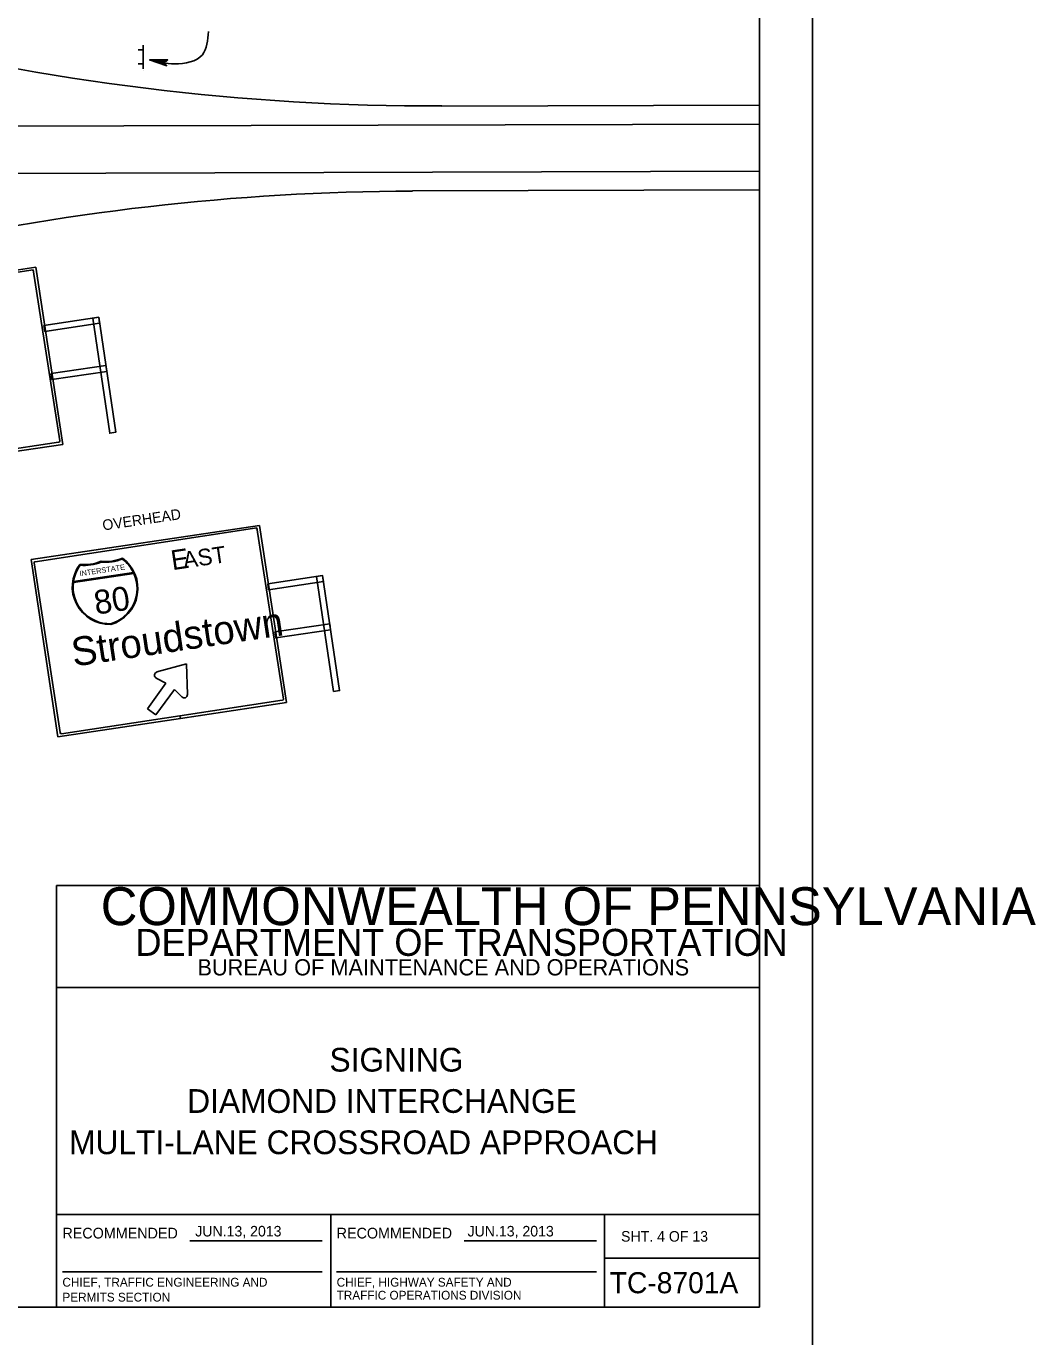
# Model space of a CAD drawing. Extents: x 644898 to 648326, y 298294 to 300670.
# Drawn here: x 648038.7 to 648325.9, y 300083.1 to 300456 of the extents above; entities that cross this region are included whole.
import ezdxf

# ---------------------------------------------------------------- set-up
doc = ezdxf.new("R2010")
doc.units = 0
for name, color, linetype in [('1', 7, 'Continuous'), ('2', 7, 'Continuous'), ('XCS-GRID-MIN', 7, 'Continuous')]:
    doc.layers.add(name, color=color, linetype=linetype)

msp = doc.modelspace()

# ---------------------------------------------------------------- linework, layer by layer
at = {"layer": '1'}
for p, q in [((648247.32, 300091.49), (648247.32, 300655.49)), ((648047.32, 300091.49), (648047.32, 300211.49)), ((648047.32, 300211.49), (648247.32, 300211.49)), ((648247.32, 300182.49), (648047.32, 300182.49)), ((648047.32, 300117.87), (648247.32, 300117.87)), ((648125.32, 300117.87), (648125.32, 300091.49)), ((648203.2, 300091.49), (648203.2, 300117.87)), ((648085.26, 300110.44), (648122.88, 300110.44)), ((648163.26, 300110.44), (648200.88, 300110.44)), ((648203.2, 300105.49), (648247.32, 300105.49)), ((648049.01, 300101.54), (648122.88, 300101.54)), ((648127.01, 300101.54), (648200.88, 300101.54)), ((648247.32, 300091.49), (647461.32, 300091.49)), ((647461.32, 300091.49), (648047.32, 300091.49))]:
    msp.add_line(p, q, dxfattribs=at)
at = {"layer": '2'}
for p, q in [((648071.95, 300450.62), (648071.95, 300443.87)), ((648071.95, 300449.24), (648070.57, 300449.24)), ((648071.95, 300445.24), (648070.57, 300445.24)), ((648071.95, 300443.49), (648071.95, 300443.49)), ((648071.95, 300443.49), (648071.95, 300443.49)), ((648156.95, 300433.24), (648247.32, 300433.51)), ((648242.07, 300433.49), (648242.07, 300433.49)), ((647844.32, 300426.99), (648247.32, 300428.13)), ((647846.32, 300413.49), (648247.32, 300414.76)), ((648148.57, 300409.12), (648247.32, 300409.38)), ((647976.44, 300377.72), (648041.41, 300387.38)), ((648048.26, 300338.02), (648040.68, 300386.7)), ((648041.41, 300387.38), (648049.11, 300337)), ((648018.78, 300333.23), (648047.9, 300337.67)), ((648049.11, 300337), (648018.89, 300332.5)), ((648040.09, 300304.24), (648105.06, 300313.9)), ((648111.92, 300264.54), (648104.33, 300313.23)), ((648105.06, 300313.9), (648112.77, 300263.52)), ((648047.7, 300253.84), (648040.09, 300304.25)), ((648065.99, 300304.39), (648065.99, 300304.39)), ((648041, 300303.26), (648048.35, 300255.06)), ((648069.23, 300300.51), (648052.19, 300298)), ((648054.06, 300302.57), (648054.06, 300302.57)), ((648060.07, 300303.49), (648060.07, 300303.49)), ((648052.17, 300297.71), (648069.3, 300300.25)), ((648084.32, 300274.56), (648075.86, 300272.27)), ((648084.55, 300265.87), (648084.32, 300274.56)), ((648078.38, 300269.07), (648073.2, 300261.79)), ((648075.56, 300260.01), (648080.89, 300267.24)), ((648075.63, 300270.44), (648078.38, 300269.07)), ((648080.89, 300267.24), (648082.95, 300265.18)), ((648082.44, 300259.76), (648111.56, 300264.2)), ((648112.77, 300263.52), (648082.55, 300259.03)), ((648048.74, 300254.69), (648082.44, 300259.76)), ((648073.2, 300261.79), (648075.56, 300260.01)), ((648082.55, 300259.03), (648082.44, 300259.76)), ((648082.44, 300259.76), (648082.55, 300259.03)), ((648082.55, 300259.03), (648047.7, 300253.84))]:
    msp.add_line(p, q, dxfattribs=at)
for points in [[(648078.45, 300444.99), (648078.32, 300445.37), (648073.82, 300446.37), (648078.45, 300444.99), (648078.7, 300444.74), (648073.82, 300446.37), (648078.45, 300445.87), (648078.7, 300446.12), (648073.82, 300446.37), (648078.95, 300446.37), (648078.7, 300446.12)], [(648040.68, 300386.7), (647977.64, 300377.08)], [(648104.33, 300313.23), (648041.29, 300303.61)]]:
    msp.add_lwpolyline(points, dxfattribs=at)
for points in [[(648043.74, 300370.85), (648059.34, 300373.16), (648059.59, 300371.45), (648043.99, 300369.13)], [(648059.34, 300373.16), (648064.2, 300340.43), (648062.49, 300340.18), (648057.63, 300372.91)], [(648045.77, 300357.14), (648061.37, 300359.46), (648061.63, 300357.75), (648046.03, 300355.43)], [(648107.39, 300297.37), (648122.99, 300299.69), (648123.25, 300297.98), (648107.64, 300295.66)], [(648122.99, 300299.69), (648127.86, 300266.96), (648126.14, 300266.71), (648121.28, 300299.43)], [(648109.43, 300283.67), (648125.03, 300285.99), (648125.28, 300284.27), (648109.68, 300281.96)]]:
    msp.add_lwpolyline(points, close=True, dxfattribs=at)
for centre, radius, start, end in [((648154.92, 301105.15), 671.88, 255.77937, 270.1682), ((648150.55, 299737.19), 671.88, 90.1683, 103.0152), ((648076.11, 300271.33), 0.915, 103.9183, 245.5492), ((648083.64, 300265.78), 0.915, 225, 1.3737)]:
    msp.add_arc(centre, radius, start, end, dxfattribs=at)
for centre, major_axis, ratio, start_param, end_param in [((648040.43, 300386.16), (-0.388, 0), 0.989072, 3.283634, 4.860778), ((648047.88, 300337.97), (0.361, 0.041), 0.980329, 4.753008, 6.326457), ((648104.08, 300312.69), (-0.388, 0), 0.989072, 3.283634, 4.860778), ((648061.23, 300316), (12.46, 0), 0.989072, 4.61309, 5.11051), ((648061.23, 300316), (12.69, 0), 0.989072, 4.617647, 5.100204), ((648059.62, 300296.01), (10.85, 0), 0.989072, 5.003697, 7.217995), ((648059.62, 300296.01), (10.62, 0), 0.989072, 0.4425, 0.922725), ((648041.33, 300303.28), (-0.388, 0), 0.989072, 4.856969, 6.450662), ((648062.66, 300296.46), (-10.85, 0), 0.989072, 5.647198, 7.861496), ((648062.66, 300296.46), (-10.62, 0), 0.989072, 5.659282, 6.139508), ((648055.16, 300315.1), (-12.46, 0), 0.989072, 1.471498, 1.968918), ((648055.16, 300315.1), (-12.69, 0), 0.989072, 1.481804, 1.964361), ((648062.66, 300296.46), (-10.62, 0), 0.989072, 6.161841, 7.861496), ((648059.62, 300296.01), (10.62, 0), 0.989072, 5.003697, 6.703352), ((648111.53, 300264.5), (0.361, 0.041), 0.980329, 4.753008, 6.326457), ((648048.7, 300255.1), (-0.402, -0.077), 0.953585, 6.234444, 7.82518)]:
    msp.add_ellipse(centre, major_axis=major_axis, ratio=ratio, start_param=start_param, end_param=end_param, dxfattribs=at)
msp.add_spline([(648090.57, 300454.49), (648088.82, 300447.87), (648080.95, 300445.24), (648073.82, 300446.37)], degree=3, dxfattribs=at)
at = {"layer": 'XCS-GRID-MIN'}
msp.add_lwpolyline([(647421.32, 300670.49), (648262.32, 300670.49), (648262.32, 300076.49), (647421.32, 300076.49)], close=True, dxfattribs=at)

# ---------------------------------------------------------------- texts
at = {"layer": '1'}
for s, height, p in [('COMMONWEALTH OF PENNSYLVANIA', 10.7828, (648059.92, 300200.22)), ('DEPARTMENT OF TRANSPORTATION', 7.6837, (648069.78, 300191.48)), ('BUREAU OF MAINTENANCE AND OPERATIONS', 4.6253, (648087.42, 300185.91)), ('SIGNING', 6.75, (648124.97, 300158.56)), ('DIAMOND INTERCHANGE', 6.75, (648084.5, 300146.81)), ('MULTI-LANE CROSSROAD APPROACH', 6.75, (648050.91, 300135.06)), ('RECOMMENDED', 3.048, (648049.01, 300111.07)), ('RECOMMENDED', 3.048, (648127.01, 300111.07)), ('SHT. 4 OF 13', 3, (648207.91, 300110.18)), ('CHIEF, TRAFFIC ENGINEERING AND', 2.5, (648049.01, 300097.38)), ('CHIEF, HIGHWAY SAFETY AND', 2.5, (648127.01, 300097.38)), ('TC-8701A', 6, (648204.69, 300095.49)), ('PERMITS SECTION', 2.5, (648049.01, 300093.13)), ('TRAFFIC OPERATIONS DIVISION', 2.5, (648127.01, 300093.68))]:
    msp.add_text(s, height=height, dxfattribs=at).set_placement(p)
at = {"layer": '2'}
for s, height, rotation, p in [('OVERHEAD', 3, 8.3729, (648060.62, 300312.48)), ('AST', 4.719, 8.4705, (648083.65, 300301.69)), ('E', 5.63, 8.4837, (648080.31, 300301.19)), ('INTERSTATE', 1.517, 8.469, (648053.99, 300299.47)), ('80', 6.829, 8.468, (648058.53, 300288.54)), ('Stroudstown', 8.1676, 8.4705, (648052.21, 300273.77))]:
    msp.add_text(s, height=height, rotation=rotation, dxfattribs=at).set_placement(p)
for p in [(648086.79, 300111.65), (648164.24, 300111.65)]:
    msp.add_text('JUN.13, 2013', height=3, dxfattribs=at).set_placement(p)

doc.saveas('drawing.dxf')
